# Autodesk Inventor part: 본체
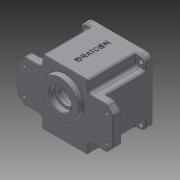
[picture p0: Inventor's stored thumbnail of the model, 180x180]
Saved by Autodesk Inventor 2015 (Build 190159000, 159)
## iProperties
Created: 2016-02
Part Number: 본체
Material: Generic
Document SubType Name: Modeling
Designer: Administrator
Density: 1 g/cm^3
Appearance: Default
Mass: 323.75 g
Surface Area: 762.764 cm^2
Volume: 323.75 cm^3
Author: Administrator
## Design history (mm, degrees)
sketch "Sketch1"
  geometry: L1 (70, 30)-(-70, 30); L2 (-70, 30)-(-70, -30); L3 (-70, -30)-(70, -30); L4 (70, -30)-(70, 30); L5 (70, 30)-(-70, -30); L6 (-70, 30)-(70, -30); 1 further point
  constraints: 12 end point, 2 midpoint, 2 parallel, 1 horizontal, 1 perpendicular
  dimensions: "d0" = 140 distance of L3.end L2.end; "d1" = 60 distance of L2.end L1.end
extrude "Extrusion1" new body sketch "Sketch1" distance "d2" = 12; taper "d3" = 0 deg
sketch "Sketch2"
  geometry: L1 (-33, -47)-(33, -47); L2 (33, -47)-(33, 47); L3 (33, 47)-(-33, 47); L4 (-33, 47)-(-33, -47); L5 (-33, -47)-(33, 47); L6 (33, -47)-(-33, 47); 1 further point
  constraints: 12 end point, 2 midpoint, 2 parallel, 1 horizontal, 1 perpendicular
  dimensions: "d4" = 66 distance of L3.end L2.end; "d5" = 94 distance of L2.end L1.end
extrude "Extrusion2" join sketch "Sketch2" distance "d6" = 79; taper "d7" = 0 deg
sketch "Sketch3"
  geometry: L1 (47, -47)-(-47, -47); L2 (-47, -47)-(-47, 47); L3 (-47, 47)-(47, 47); L4 (47, 47)-(47, -47); L5 (47, -47)-(-47, 47); L6 (-47, -47)-(47, 47); 1 further point
  constraints: 12 end point, 2 midpoint, 2 parallel, 1 horizontal, 1 perpendicular
  dimensions: "d8" = 94 distance of L2.end L3.end; "d9" = 94 distance of L1.end L2.end
extrude "Extrusion3" join sketch "Sketch3" distance "d10" = 10; taper "d11" = 0 deg
sketch "Sketch4"
  geometry: L1 (-47, 30)-(-33, 30); L2 (-33, 30)-(-33, -30); L3 (-33, -30)-(-47, -30); L4 (-47, -30)-(-47, 30); L5 (33, 30)-(47, 30); L6 (47, 30)-(47, -30); L7 (47, -30)-(33, -30); L8 (33, -30)-(33, 30); L9 (-47, 47)-(-47, -47) reference; L10 (47, -47)-(47, 47) reference; 1 further point
  constraints: 16 end point, 4 parallel, 2 collinear, 2 equal length, 2 horizontal, 2 perpendicular
  dimensions: "d12" = 60 distance of L3.end L1.start; "d13" = 30 distance from line of point (0, 0) L1; "d14" = 14 distance of L1.start L1.end; "d15" = 30 distance from line of L5 point (0, 0)
extrude "Extrusion4" join sketch "Sketch4" stored distance "d16" = 10; taper "d17" = 0 deg
chamfer "Chamfer1" distance "d18" = 10; stored, may be unused: second distance "d19" = 2, angle "d20" = 45 deg
sketch "Sketch5"
  geometry: 2 further points
  constraints: 1 coincident
hole "Hole1" sketch "Sketch5" at (0, 0) diameter "d21" = 80; stored, may be unused: countersink angle "d25" = 90 deg, drill point angle "d27" = 0 deg; dims "d22" = 6, "d23" = 86, "d24" = 9, "d26" = 71
sketch "Sketch6"
  geometry: C1 r 21 at (0, -11); C2 r 15 at (0, 20); 1 further point
  constraints: 2 centre point, 2 vertical alignment
  dimensions: "d28" = 11 distance of C1.centre point (0, 0); "d29" = 20 distance of C2.centre point (0, 0); "d30" = 42 diameter of C1; "d31" = 30 diameter of C2
extrude "Extrusion5" join sketch "Sketch6" distance "d32" = 7; taper "d33" = 0 deg
hole "Hole2" diameter "d40" = 25; stored, may be unused: countersink angle "d44" = 90 deg, drill point angle "d46" = 0 deg; dims "d38" = 10, "d39" = 10, "d41" = 6, "d42" = 35, "d43" = 10, "d45" = 15
hole "Hole4" diameter "d58" = 19; stored, may be unused: countersink angle "d62" = 90 deg, drill point angle "d64" = 0 deg; dims "d56" = 10, "d57" = 10, "d59" = 6, "d60" = 22, "d61" = 7, "d63" = 8
sketch "Sketch8"
  geometry: A1 r 36 centre (0, 0) between (-36, 0) and (-35.778, -3.995); A2 r 40 centre (0, 0) between (-39.148, -8.214) and (-39.148, 8.214); A3 r 4 centre (-36, 0) between (-35.852, -3.997) and (-35.852, 3.997); A4 r 3.5 centre (-35.722, -7.495) between (-35.778, -3.995) and (-39.148, -8.214); A5 r 3.5 centre (-35.722, 7.495) between (-39.148, 8.214) and (-35.778, 3.995); A6 r 4 centre (36, 0) between (35.852, 3.997) and (35.852, -3.997); A7 r 3.5 centre (35.722, -7.495) between (39.148, -8.214) and (35.778, -3.995); A8 r 3.5 centre (35.722, 7.495) between (35.778, 3.995) and (39.148, 8.214); 1 further point
  constraints: 26 point on circle, 8 centre point, 8 tangent, 2 coincident, 2 horizontal alignment
  dimensions: "d65" = 36 radius of A1; "d66" = 40 radius of A2; "d67" = 4 radius of A3; "d68" = 3.5 radius of A4; "d69" = 3.5 radius of A5; "d70" = 4 radius of A6; "d71" = 3.5 radius of A7; "d72" = 3.5 radius of A8
extrude "Extrusion7" join sketch "Sketch8" stored distance "d73" = 7; taper "d74" = 0 deg
sketch "Sketch9"
  geometry: L1 (40, 40)-(-40, 40); L2 (-40, 40)-(-40, -40); L3 (-40, -40)-(40, -40); L4 (40, -40)-(40, 40); L5 (40, 40)-(-40, -40); L6 (-40, 40)-(40, -40); 5 further points
  constraints: 12 end point, 4 coincident, 2 midpoint, 2 parallel, 1 horizontal, 1 perpendicular
  dimensions: "d75" = 80 distance of L3.end L2.end; "d76" = 80 distance of L2.end L1.end
hole "Hole5" sketch "Sketch9" at (40, -40), (-40, -40), (-40, 40), (40, 40) diameter "d77" = 7; stored, may be unused: countersink angle "d81" = 90 deg, drill point angle "d83" = 0 deg; dims "d78" = 6, "d79" = 22, "d80" = 7, "d82" = 10
sketch "Sketch10"
  geometry: A1 r 4 centre (36, 0) between (35.852, 3.997) and (35.852, -3.997) reference; A2 r 4 centre (-36, 0) between (-35.852, -3.997) and (-35.852, 3.997) reference; 3 further points
  constraints: 2 coincident
hole "Hole6" sketch "Sketch10" at (36, 0), (-36, 0) diameter "d84" = 3.242; stored, may be unused: countersink angle "d88" = 90 deg, drill point angle "d90" = 118 deg; dims "d85" = 7, "d86" = 22, "d87" = 7, "d89" = 9
sketch "Sketch11"
  geometry: L1 (60, -19)-(-60, -19); L2 (-60, -19)-(-60, 19); L3 (-60, 19)-(60, 19); L4 (60, 19)-(60, -19); L5 (60, -19)-(-60, 19); L6 (-60, -19)-(60, 19); 5 further points
  constraints: 12 end point, 4 coincident, 2 midpoint, 2 parallel, 1 horizontal, 1 perpendicular
  dimensions: "d91" = 120 distance of L2.end L3.end; "d92" = 38 distance of L1.end L2.end
hole "Hole7" sketch "Sketch11" at (60, -19), (60, 19), (-60, 19), (-60, -19) diameter "d93" = 5; stored, may be unused: countersink angle "d97" = 90 deg, drill point angle "d99" = 0 deg; dims "d94" = 7, "d95" = 9, "d96" = 4, "d98" = 9
chamfer "Chamfer2" distance "d100" = 1; stored, may be unused: second distance "d101" = 2, angle "d102" = 45 deg
fillet "Fillet1" dims "d103" = 0.3
fillet "Fillet2" dims "d104" = 3
fillet "Fillet3" dims "d105" = 2
fillet "Fillet5" dims "d139" = 2
fillet "Fillet6" dims "d140" = 8
fillet "Fillet7" dims "d141" = 2
fillet "Fillet8" dims "d142" = 5
fillet "Fillet9" dims "d143" = 2
sketch "Sketch21"
  geometry: L1 (70, -79)-(8, -79) reference; L2 (78, 0)-(0, 0) reference; 3 further points
  constraints: 1 midpoint, 1 vertical alignment, 1 other
  dimensions: "d165" = 40 distance from line of L2 point (39, -40)
emboss "Emboss1" sketch "Sketch21" dims "d8" = 94, "d9" = 94, "d166" = 0.5, "d167" = 0
fillet "Fillet12" dims "d168" = 5
sketch "Sketch23"
  geometry: L1 (-68.536, 21.464)-(-61.464, 28.536) reference; L2 (-70, -17.929)-(-70, 17.929) reference; L3 (-61.464, -28.536)-(-68.536, -21.464) reference; L4 (-38, -30)-(-57.929, -30) reference; L5 (-33, -35)-(-33, -45) reference; L6 (-31, -47)-(31, -47) reference; L7 (33, -45)-(33, -35) reference; L8 (57.929, -30)-(38, -30) reference; L9 (68.536, -21.464)-(61.464, -28.536) reference; L10 (70, 17.929)-(70, -17.929) reference; L11 (61.464, 28.536)-(68.536, 21.464) reference; L12 (38, 30)-(57.929, 30) reference; L13 (33, 35)-(33, 45) reference; L14 (31, 47)-(-31, 47) reference; L15 (-33, 45)-(-33, 35) reference; L16 (-57.929, 30)-(-38, 30) reference; L17 (-31, 46)-(31, 46); L18 (32, 45)-(32, 35); L19 (38, 29)-(57.929, 29); L20 (60.757, 27.828)-(67.828, 20.757); L21 (69, 17.929)-(69, -17.929); L22 (67.828, -20.757)-(60.757, -27.828); L23 (57.929, -29)-(38, -29); L24 (32, -35)-(32, -45); L25 (31, -46)-(-31, -46); L26 (-32, -45)-(-32, -35); L27 (-38, -29)-(-57.929, -29); L28 (-60.757, -27.828)-(-67.828, -20.757); L29 (-69, -17.929)-(-69, 17.929); L30 (-67.828, 20.757)-(-60.757, 27.828); L31 (-57.929, 29)-(-38, 29); L32 (-32, 35)-(-32, 45); C1 r 2.5 at (-60, -19) reference; C2 r 2.5 at (60, 19) reference; C3 r 2.5 at (60, -19) reference; C4 r 2.5 at (-60, 19) reference; C5 r 12.5 at (0, 11) reference; A1 r 5 centre (-57.929, 25) between (-57.929, 30) and (-61.464, 28.536) reference; A2 r 5 centre (-65, 17.929) between (-68.536, 21.464) and (-70, 17.929) reference; A3 r 5 centre (-65, -17.929) between (-70, -17.929) and (-68.536, -21.464) reference; A4 r 5 centre (-57.929, -25) between (-61.464, -28.536) and (-57.929, -30) reference; A5 r 5 centre (-38, -35) between (-33, -35) and (-38, -30) reference; A6 r 2 centre (-31, -45) between (-33, -45) and (-31, -47) reference; A7 r 2 centre (31, -45) between (31, -47) and (33, -45) reference; A8 r 5 centre (38, -35) between (38, -30) and (33, -35) reference; A9 r 5 centre (57.929, -25) between (57.929, -30) and (61.464, -28.536) reference; A10 r 5 centre (65, -17.929) between (68.536, -21.464) and (70, -17.929) reference; A11 r 5 centre (65, 17.929) between (70, 17.929) and (68.536, 21.464) reference; A12 r 5 centre (57.929, 25) between (61.464, 28.536) and (57.929, 30) reference; A13 r 5 centre (38, 35) between (33, 35) and (38, 30) reference; A14 r 2 centre (31, 45) between (33, 45) and (31, 47) reference; A15 r 2 centre (-31, 45) between (-31, 47) and (-33, 45) reference; A16 r 5 centre (-38, 35) between (-38, 30) and (-33, 35) reference; A17 r 1 centre (31, 45) between (32, 45) and (31, 46); A18 r 6 centre (38, 35) between (32, 35) and (38, 29); A19 r 4 centre (57.929, 25) between (60.757, 27.828) and (57.929, 29); A20 r 4 centre (65, 17.929) between (69, 17.929) and (67.828, 20.757); A21 r 4 centre (65, -17.929) between (67.828, -20.757) and (69, -17.929); A22 r 4 centre (57.929, -25) between (57.929, -29) and (60.757, -27.828); A23 r 6 centre (38, -35) between (38, -29) and (32, -35); A24 r 1 centre (31, -45) between (31, -46) and (32, -45); A25 r 1 centre (-31, -45) between (-32, -45) and (-31, -46); A26 r 6 centre (-38, -35) between (-32, -35) and (-38, -29); A27 r 4 centre (-57.929, -25) between (-60.757, -27.828) and (-57.929, -29); A28 r 4 centre (-65, -17.929) between (-69, -17.929) and (-67.828, -20.757); A29 r 4 centre (-65, 17.929) between (-67.828, 20.757) and (-69, 17.929); A30 r 4 centre (-57.929, 25) between (-57.929, 29) and (-60.757, 27.828); A31 r 6 centre (-38, 35) between (-38, 29) and (-32, 35); A32 r 1 centre (-31, 45) between (-31, 46) and (-32, 45); 1 further point
  constraints: 32 end point, 32 point on circle, 16 centre point, 31 other
  dimensions: "d169" = 1 distance between parallel lines of L14 L17
extrude "Extrusion13" join sketch "Sketch23" distance "d170" = 1; taper "d171" = 0 deg
sketch "Sketch24"
  geometry: C1 r 28 at (0, 11); 1 further point
  constraints: 1 centre point, 1 vertical alignment
  dimensions: "d172" = 28 radius of C1; "d173" = 11 distance of point (0, 0) C1.centre
extrude "Extrusion14" join sketch "Sketch24" distance "d174" = 7; taper "d175" = -10 deg
hole "Hole10" diameter "d178" = 32; stored, may be unused: countersink angle "d182" = 90 deg, drill point angle "d184" = 0 deg; dims "d176" = 10, "d177" = 10, "d179" = 7, "d180" = 32, "d181" = 8, "d183" = 8
fillet "Fillet13" dims "d185" = 0.3
chamfer "Chamfer5" distance "d186" = 1; stored, may be unused: second distance "d187" = 2, angle "d188" = 45 deg
fillet "Fillet14" dims "d189" = 0.3
chamfer "Chamfer6" distance "d190" = 1; stored, may be unused: second distance "d191" = 2, angle "d192" = 45 deg
body "Solid1"
node "Projected Loop3"
